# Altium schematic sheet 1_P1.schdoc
size 309 x 223 mm; Symbol: Sheet-Symbol_A4; Device: Sheet-Symbol_A4; @Page Name: P1; @Create Date: 2023-06-18; @Page Count: 1; @Page No: 1; @Project Name: usrp2040-series; @Schematic Name: Schematic1; @Update Date: 2023-06-18; Company: 嘉立创EDA; Page Size: A4; Version: V1.0
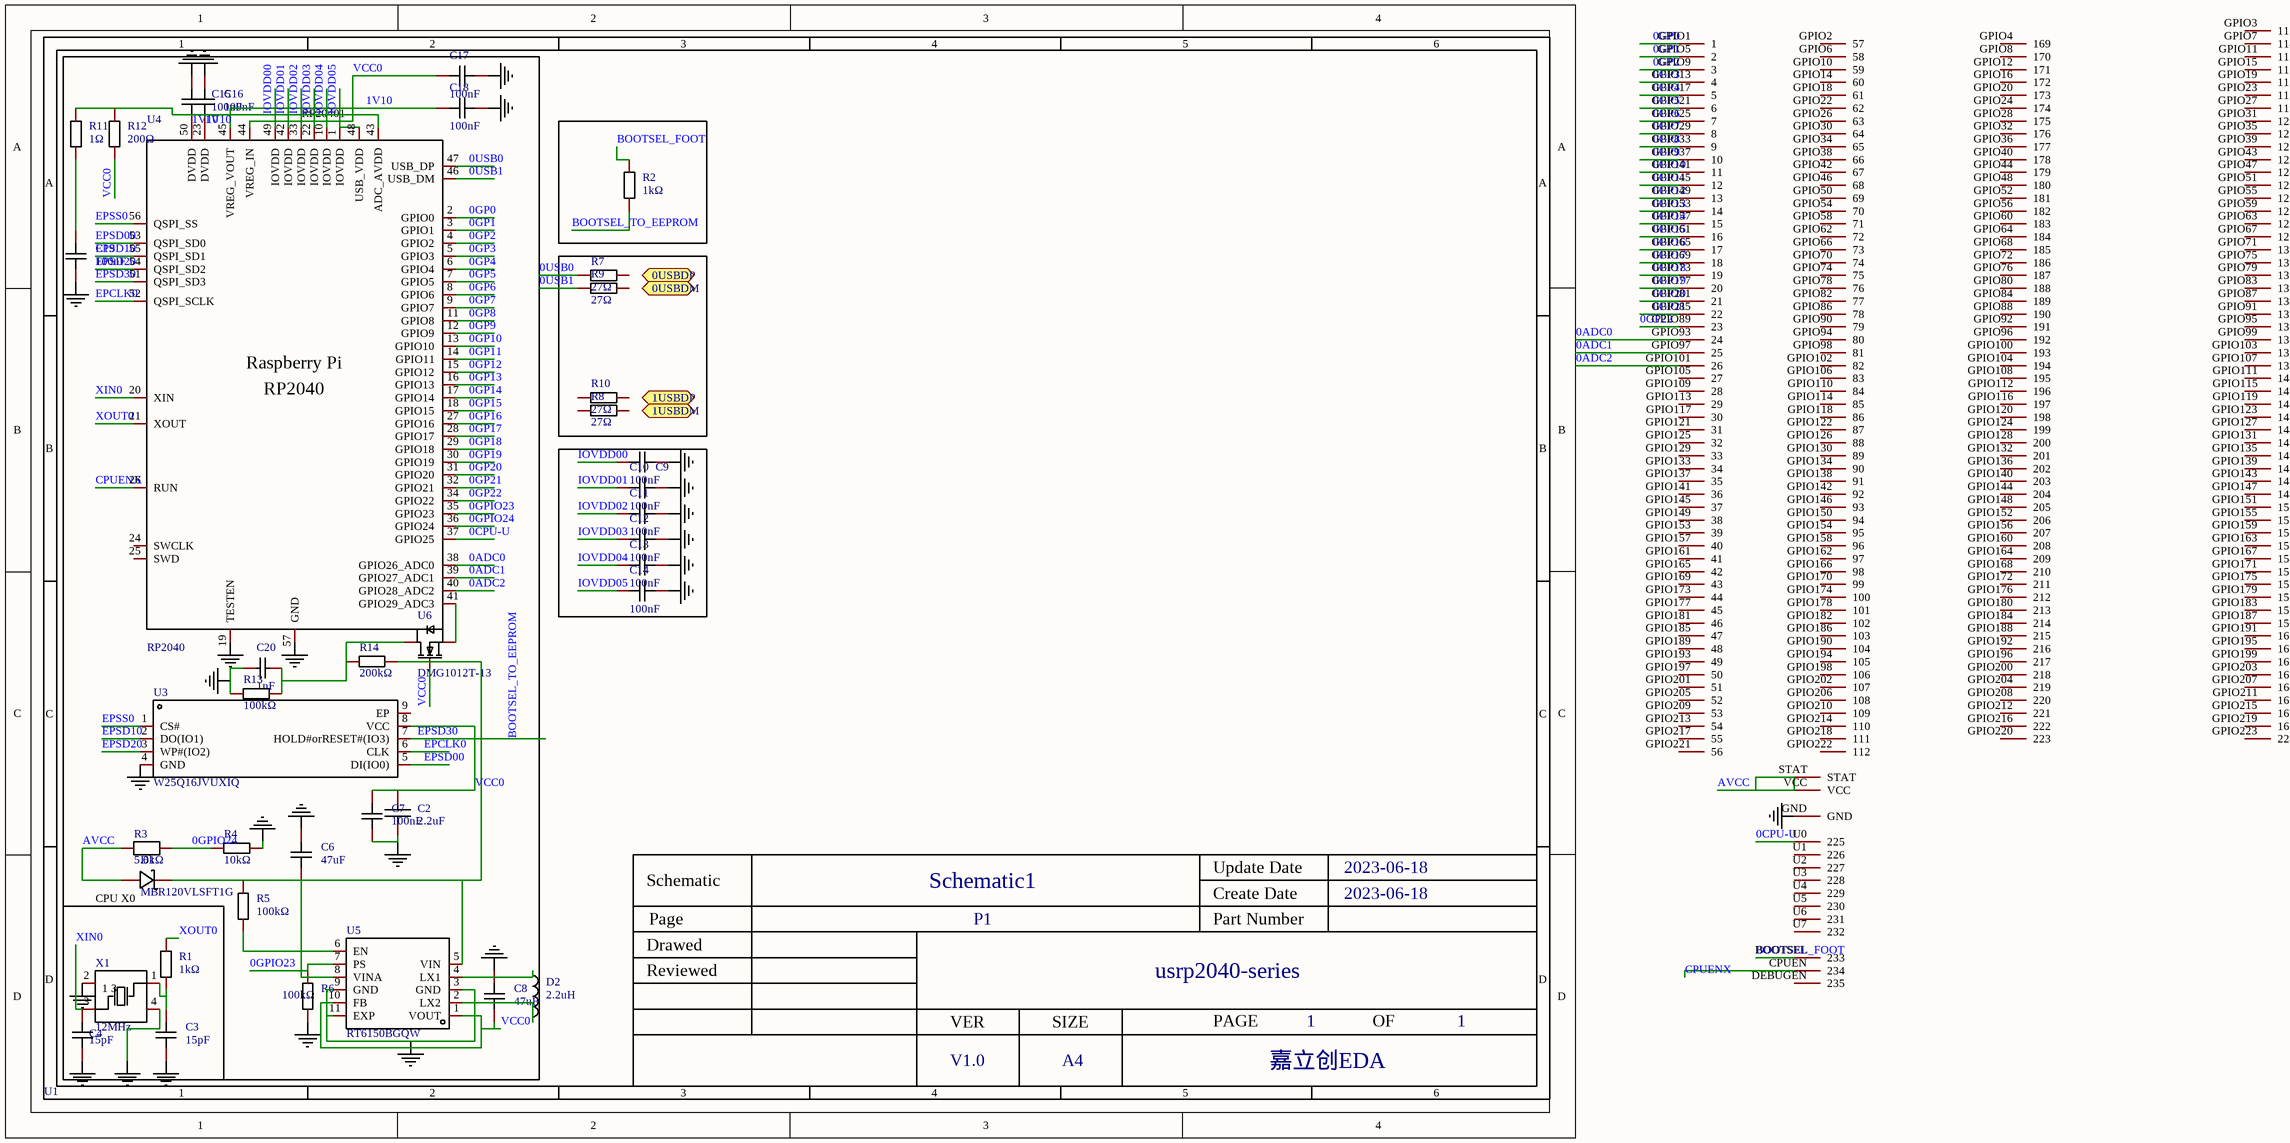
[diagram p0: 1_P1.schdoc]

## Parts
C2  2.2uF  [C0402]
C3  15pF  [C0201]
C4  15pF  [C0201]
C6  47uF  [C0805]
C7  100nF  [C0201]
C8  47uF  [C0805]
C9  100nF  [C0201]
C10  100nF  [C0201]
C11  100nF  [C0201]
C12  100nF  [C0201]
C13  100nF  [C0201]
C14  100nF  [C0201]
C15  100nF  [C0201]
C16  100nF  [C0201]
C17  100nF  [C0201]
C18  100nF  [C0201]
C19  100nF  [C0201]
C20  1nF  [C0201]
D1  MBR120VLSFT1G  [SOD-123F_L2.8-W1.8-LS3.7-RD]
D2  2.2uH  [IND-SMD_L2.5-W2.0]
R1  1kΩ  [R0402]
R2  1kΩ  [R0402]
R3  5.6kΩ  [R0402]
R4  10kΩ  [R0603]
R5  100kΩ  [R0402]
R6  100kΩ  [R0402]
R7  27Ω  [R0201]
R8  27Ω  [R0201]
R9  27Ω  [R0201]
R10  27Ω  [R0201]
R11  1Ω  [R0402]
R12  200Ω  [R0603]
R13  100kΩ  [R0402]
R14  200kΩ  [R0402]
U1  USRP2040V1  (value not drawn)
U3  W25Q16JVUXIQ  [USON-8_L3.0-W2.0-P0.50-BL-EP]
U4  RP2040  [LQFN-56_L7.0-W7.0-P0.4-EP]
U5  RT6150BGQW  [WSON-10_L2.5-W2.5-P0.50-BL-EP]
U6  DMG1012T-13  [SOT-523-3_L1.6-W0.8-P1.00-LS1.6-BR]
X1  12MHz  [CRYSTAL-SMD_4P-L3.2-W2.5-BL]

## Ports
0USBDM (bidir), 0USBDP (bidir), 1USBDM (bidir), 1USBDP (bidir)

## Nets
NetC2_2: C2.2 C3.1 C4.1 C6.1 C7.1 C8.2 C9.2 C10.2 C11.2 C12.2 C13.2 C14.2 C15.1 C16.2 C17.1 C18.1 C19.1 C20.1 R4.2 R6.1 R13.1 U1.GND U3.4(GND) U4.19(TESTEN) U4.57(GND) U5.3(GND) U5.9(GND) U5.11(EXP) X1.2(GND) X1.4(GND)
0ADC0: U1.GPIO93(24) U4.38(GPIO26_ADC0)
0ADC1: U1.GPIO97(25) U4.39(GPIO27_ADC1)
0ADC2: U1.GPIO101(26) U4.40(GPIO28_ADC2)
0CPU-U: U1.U0(225) U4.37(GPIO25)
0GP0: U1.GPIO1(1) U4.2(GPIO0)
0GP1: U1.GPIO5(2) U4.3(GPIO1)
0GP2: U1.GPIO9(3) U4.4(GPIO2)
0GP3: U1.GPIO13(4) U4.5(GPIO3)
0GP4: U1.GPIO17(5) U4.6(GPIO4)
0GP5: U1.GPIO21(6) U4.7(GPIO5)
0GP6: U1.GPIO25(7) U4.8(GPIO6)
0GP7: U1.GPIO29(8) U4.9(GPIO7)
0GP8: U1.GPIO33(9) U4.11(GPIO8)
0GP9: U1.GPIO37(10) U4.12(GPIO9)
0GP10: U1.GPIO41(11) U4.13(GPIO10)
0GP11: U1.GPIO45(12) U4.14(GPIO11)
0GP12: U1.GPIO49(13) U4.15(GPIO12)
0GP13: U1.GPIO53(14) U4.16(GPIO13)
0GP14: U1.GPIO57(15) U4.17(GPIO14)
0GP15: U1.GPIO61(16) U4.18(GPIO15)
0GP16: U1.GPIO65(17) U4.27(GPIO16)
0GP17: U1.GPIO69(18) U4.28(GPIO17)
0GP18: U1.GPIO73(19) U4.29(GPIO18)
0GP19: U1.GPIO77(20) U4.30(GPIO19)
0GP20: U1.GPIO81(21) U4.31(GPIO20)
0GP21: U1.GPIO85(22) U4.32(GPIO21)
0GP22: U1.GPIO89(23) U4.34(GPIO22)
0GPIO23: R6.2 U4.35(GPIO23) U5.7(PS)
0GPIO24: R3.1 R4.1 U4.36(GPIO24)
0USB0: R7.1 U4.47(USB_DP)
0USB1: R9.1 U4.46(USB_DM)
1V10: C15.2 C16.1 C18.2 U4.23(DVDD) U4.45(VREG_VOUT) U4.50(DVDD)
AVCC: D1.2(A) R3.2 U1.STAT U1.VCC
BOOTSEL_FOOT: R2.2 U1.BOOTSEL(233)
BOOTSEL_TO_EEPROM: C6.2 D1.1(K) R2.1 R5.2 R14.2 U3.7(HOLD#orRESET#(IO3)) U4.51(QSPI_SD3) U5.5(VIN) U5.8(VINA)  [also labelled EPSD30]
CPUENX: U1.CPUEN(234) U4.26(RUN)
EPCLK0: U3.6(CLK) U4.52(QSPI_SCLK)
EPSD00: U3.5(DI(IO0)) U4.53(QSPI_SD0)
EPSD10: U3.2(DO(IO1)) U4.55(QSPI_SD1)
EPSD20: U3.3(WP#(IO2)) U4.54(QSPI_SD2)
EPSS0: U3.1(CS#) U4.56(QSPI_SS)
IOVDD00: C9.1 C10.1 C11.1 C12.1 C13.1 C14.1 R11.2 R12.2 U4.1(IOVDD) U4.10(IOVDD) U4.22(IOVDD) U4.33(IOVDD) U4.42(IOVDD) U4.43(ADC_AVDD) U4.48(USB_VDD) U4.49(IOVDD)  [also labelled IOVDD01, IOVDD02, IOVDD03, IOVDD04, IOVDD05]
VCC0: C2.1 C7.2 C8.1 C17.2 R12.1 U3.8(VCC) U4.44(VREG_IN) U5.1(VOUT) U5.10(FB) U6.1(G)
XIN0: C4.2 U4.20(XIN) X1.3(OSC2)
XOUT0: R1.2 U4.21(XOUT)
NetC3_2: C3.2 R1.1 X1.1(OSC1)
NetC19_2: C19.2 R11.1
NetC20_2: C20.2 R13.2 R14.1 U6.3(D)
NetD2_1: D2.1 U5.4(LX1)
NetD2_2: D2.2 U5.2(LX2)
NetR5_1: R5.1 U5.6(EN)
NetU4_41: U4.41(GPIO29_ADC3) U6.2(S)

Not connected (* = marked no-connect by the designer): R7 2; R8 1 2; R9 2; R10 1 2; U1 DEBUGEN(235) GPIO2(57) GPIO3(113) GPIO4(169) GPIO6(58) GPIO7(114) GPIO8(170) GPIO10(59) GPIO11(115) GPIO12(171) GPIO14(60) GPIO15(116) GPIO16(172) GPIO18(61) GPIO19(117) GPIO20(173) GPIO22(62) GPIO23(118) GPIO24(174) GPIO26(63) GPIO27(119) GPIO28(175) GPIO30(64) GPIO31(120) GPIO32(176) GPIO34(65) GPIO35(121) GPIO36(177) GPIO38(66) GPIO39(122) GPIO40(178) GPIO42(67) GPIO43(123) GPIO44(179) GPIO46(68) GPIO47(124) GPIO48(180) GPIO50(69) GPIO51(125) GPIO52(181) GPIO54(70) GPIO55(126) GPIO56(182) GPIO58(71) GPIO59(127) GPIO60(183) GPIO62(72) GPIO63(128) GPIO64(184) GPIO66(73) GPIO67(129) GPIO68(185) GPIO70(74) GPIO71(130) GPIO72(186) GPIO74(75) GPIO75(131) GPIO76(187) GPIO78(76) GPIO79(132) GPIO80(188) GPIO82(77) GPIO83(133) GPIO84(189) GPIO86(78) GPIO87(134) GPIO88(190) GPIO90(79) GPIO91(135) GPIO92(191) GPIO94(80) GPIO95(136) GPIO96(192) GPIO98(81) GPIO99(137) GPIO100(193) GPIO102(82) GPIO103(138) GPIO104(194) GPIO105(27) GPIO106(83) GPIO107(139) GPIO108(195) GPIO109(28) GPIO110(84) GPIO111(140) GPIO112(196) GPIO113(29) GPIO114(85) GPIO115(141) GPIO116(197) GPIO117(30) GPIO118(86) GPIO119(142) GPIO120(198) GPIO121(31) GPIO122(87) GPIO123(143) GPIO124(199) GPIO125(32) GPIO126(88) GPIO127(144) GPIO128(200) GPIO129(33) GPIO130(89) GPIO131(145) GPIO132(201) GPIO133(34) GPIO134(90) GPIO135(146) GPIO136(202) GPIO137(35) GPIO138(91) GPIO139(147) GPIO140(203) GPIO141(36) GPIO142(92) GPIO143(148) GPIO144(204) GPIO145(37) GPIO146(93) GPIO147(149) GPIO148(205) GPIO149(38) GPIO150(94) GPIO151(150) GPIO152(206) GPIO153(39) GPIO154(95) GPIO155(151) GPIO156(207) GPIO157(40) GPIO158(96) GPIO159(152) GPIO160(208) GPIO161(41) GPIO162(97) GPIO163(153) GPIO164(209) GPIO165(42) GPIO166(98) GPIO167(154) GPIO168(210) GPIO169(43) GPIO170(99) GPIO171(155) GPIO172(211) GPIO173(44) GPIO174(100) GPIO175(156) GPIO176(212) GPIO177(45) GPIO178(101) GPIO179(157) GPIO180(213) GPIO181(46) GPIO182(102) GPIO183(158) GPIO184(214) GPIO185(47) GPIO186(103) GPIO187(159) GPIO188(215) GPIO189(48) GPIO190(104) GPIO191(160) GPIO192(216) GPIO193(49) GPIO194(105) GPIO195(161) GPIO196(217) GPIO197(50) GPIO198(106) GPIO199(162) GPIO200(218) GPIO201(51) GPIO202(107) GPIO203(163) GPIO204(219) GPIO205(52) GPIO206(108) GPIO207(164) GPIO208(220) GPIO209(53) GPIO210(109) GPIO211(165) GPIO212(221) GPIO213(54) GPIO214(110) GPIO215(166) GPIO216(222) GPIO217(55) GPIO218(111) GPIO219(167) GPIO220(223) GPIO221(56) GPIO222(112) GPIO223(224) U1(226) U2(227) U3(228) U4(229) U5(230) U6(231) U7(232); U3 9(EP); U4 24(SWCLK) 25(SWD)

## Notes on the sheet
- (near U4) RP20401
- (near D1) CPU X0
- (near X1) 1 3

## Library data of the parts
C2 = CL05A225MQ5NSNC: 容值:2.2uF;精度:±20%;额定电压:6.3V;材质(温度系数):X5R;; Manufacturer: SAMSUNG(三星); Add into BOM: yes; Tolerance: ±20%; Voltage Rated: 6.3V; Temperature Coefficient: X5R
C3 C4 = CL03C150JA3ANNC: 容值:15pF;精度:±5%;额定电压:25V;材质(温度系数):C0G;; Manufacturer: SAMSUNG(三星); Add into BOM: yes; Tolerance: ±5%; Voltage Rated: 25V; Temperature Coefficient: C0G
C6 C8 = GRM21BR60J476ME01L: 容值:47uF;精度:±20%;额定电压:6.3V;材质(温度系数):X5R;; Manufacturer: muRata(村田); Add into BOM: yes; Tolerance: ±20%; Voltage Rated: 6.3V; Temperature Coefficient: X5R
C7 C9-C19 = GRM033R60J104KE19D: 容值:100nF;精度:±10%;额定电压:6.3V;材质(温度系数):X5R;; Manufacturer: muRata(村田); Add into BOM: yes; Tolerance: ±10%; Voltage Rated: 6.3V; Temperature Coefficient: X5R
C20 = GRM033R71E102KA01D: 容值:1nF;精度:±10%;额定电压:25V;材质(温度系数):X7R;; Manufacturer: muRata(村田); Add into BOM: yes; Tolerance: ±10%; Voltage Rated: 25V; Temperature Coefficient: X7R
D1 = MBR120VLSFT1G: 直流反向耐压(Vr):20V;平均整流电流(Io):1A;正向压降(Vf):300mV@1A;; Manufacturer: onsemi(安森美); Add into BOM: yes; Reverse Voltage (Vr): 20V; Average Rectified Current (Io): 1A
D2 = SRN2512-2R2M: 电感值:2.2uH;精度:±20%;额定电流:2.3A;饱和电流(Isat):2.7A;直流电阻(DCR):102mΩ;; Manufacturer: BOURNS; Add into BOM: yes; Tolerance: ±20%; Rated Current: 2.3A; Saturation Current (Isat): 2.7A; DC Resistance (DCR): 102mΩ; Q @ Freq: 11@1MHz; Frequency - Self Resonant: 80MHz
R1 R2 = AECR0402F1K00K9: 电阻类型:厚膜电阻;阻值:1kΩ;精度:±1%;功率:63mW;; Manufacturer: RESI(开步睿思）; Add into BOM: yes; Tolerance: ±1%; Power(Watts): 63mW; Temperature Coefficient: ±100ppm/℃; Overload Voltage (Max): 50V
R3 = CR0402F5K60Q10Z: 阻值:5.6kΩ;精度:±1%;功率:63mW;; Manufacturer: EVER OHMS(天二科技); Add into BOM: yes; Tolerance: ±1%; Power(Watts): 63mW; Temperature Coefficient: ±100ppm/℃
R4 = 0603WAF1002T5E: 电阻类型:厚膜电阻;阻值:10kΩ;精度:±1%;功率:100mW;; Manufacturer: UNI-ROYAL(厚声); Add into BOM: yes; Tolerance: ±1%; Power(Watts): 100mW; Temperature Coefficient: ±100ppm/℃; Overload Voltage (Max): 75V
R5 R6 R13 = RC0402FR-07100KL: 电阻类型:厚膜电阻;阻值:100kΩ;精度:±1%;功率:62.5mW;; Manufacturer: YAGEO(国巨); Add into BOM: yes; Tolerance: ±1%; Power(Watts): 62.5mW; Temperature Coefficient: ±100ppm/℃; Overload Voltage (Max): 50V
R7-R10 = RC0201FR-0727RL: 电阻类型:厚膜电阻;阻值:27Ω;精度:±1%;功率:50mW;; Manufacturer: YAGEO(国巨); Add into BOM: yes; Tolerance: ±1%; Power(Watts): 50mW; Temperature Coefficient: ±200ppm/℃; Overload Voltage (Max): 25V
R11 = RC0402FR-071RL: 电阻类型:厚膜电阻;阻值:1Ω;精度:±1%;功率:62.5mW;; Manufacturer: YAGEO(国巨); Add into BOM: yes; Tolerance: ±1%; Power(Watts): 62.5mW; Temperature Coefficient: ±200ppm/℃; Overload Voltage (Max): 50V
R12 = RC0603FR-07200RL: 电阻类型:厚膜电阻;阻值:200Ω;精度:±1%;功率:100mW;; Manufacturer: YAGEO(国巨); Add into BOM: yes; Tolerance: ±1%; Power(Watts): 100mW; Temperature Coefficient: ±100ppm/℃; Overload Voltage (Max): 75V
R14 = RC0402FR-07200KL: 电阻类型:厚膜电阻;阻值:200kΩ;精度:±1%;功率:62.5mW;; Manufacturer: YAGEO(国巨); Add into BOM: yes; Tolerance: ±1%; Power(Watts): 62.5mW; Temperature Coefficient: ±100ppm/℃; Overload Voltage (Max): 50V
U3 = W25Q16JVUXIQ: Manufacturer: WINBOND(华邦); Add into BOM: no; Convert to PCB: yes
U4 = RP2040_C2040: 应用领域:-;CPU内核:ARM-M系列;CPU最大主频:133MHz;工作电压范围:-;程序存储容量:-;程序存储器类型:-;RAM总容量:264KB;GPIO端口数量:30;; Manufacturer: Raspberry Pi(树莓派); Add into BOM: no; Convert to PCB: yes; CPU Maximum Speed: 133MHz; RAM Size: 264KB; GPIO Ports Number: 30; ADC (Bit): 12bit; UART/USART: 2; Universal Serial Bus: 有; Peripheral/Function: DMA；PWM
U5 = RT6150BGQW: 功能类型:升降压型;同步整流:是;输出通道数:1;拓扑结构:降压-升压式;输入电压:1.8V~5.5V;输出电压:1.8V~5.5V;输出电流(最大值):800mA;开关频率:1MHz;; Manufacturer: RICHTEK(立锜); Add into BOM: yes; Function: 升降压型; Synchronous Rectification: 是; Number of Outputs: 1; Topology: 降压-升压式; Output Current (Max): 800mA; Switching Frequency: 1MHz
U6 = DMG1012T-13: 类型:N沟道;漏源电压(Vdss):20V;连续漏极电流(Id):630mA;功率(Pd):280mW;导通电阻(RDS(on)@Vgs,Id):400mΩ@600mA,4.5V;; Manufacturer: DIODES(美台); Add into BOM: yes; Drain Source Voltage (Vdss): 20V; Continuous Drain Current (Id): 630mA; Power Dissipation (Pd): 280mW; Gate Threshold Voltage (Vgs(th)@Id): 1V@250uA; Total Gate Charge (Qg@Vgs): 737pC@4.5V; Input Capacitance (Ciss@Vds): 60.67pF@16V
X1 = X322512MMB4SI: 频率:12MHz;频率公差:±10ppm;负载电容:10pF;; Manufacturer: YXC(扬兴晶振); Add into BOM: yes; Crystal Type: 贴片无源晶振; Frequency Tolerance: ±10ppm; Frequency Stability: ±30ppm; Load Capacitance: 10pF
